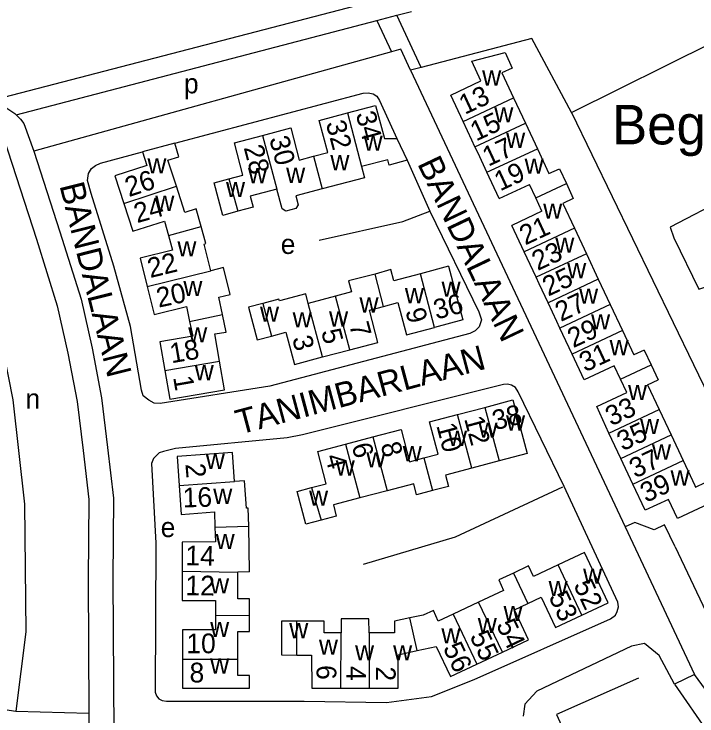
# Model space of a CAD drawing. Extents: x 162883 to 165538, y 383986 to 385172.
# Drawn here: x 163773.3 to 163911.8, y 384315.2 to 384457.6 of the extents above; entities that cross this region are included whole.
import ezdxf

# ---------------------------------------------------------------- set-up
doc = ezdxf.new("R2010")
doc.units = 0
for name, color, linetype in [('BLT_Basislijn', 7, 'Continuous'), ('BLT_Bebouwing', 7, 'Continuous'), ('BLT_Centroide', 7, 'Continuous'), ('BLT_Huisnummer', 7, 'Continuous'), ('BLT_Huisnummer_ tussenligend', 7, 'Continuous'), ('BLT_Onderverdeling_panden', 7, 'Continuous'), ('BLT_Straatnaam', 7, 'Continuous'), ('BLT_Terrein_beschrifting', 7, 'Continuous')]:
    doc.layers.add(name, color=color, linetype=linetype)

msp = doc.modelspace()

# ---------------------------------------------------------------- linework, layer by layer
at = {"layer": 'BLT_Basislijn'}
for p, q in [((163886.33, 384437.63), (163943.9, 384466.17)), ((163850.89, 384457.34), (163853.91, 384458.13)), ((163773.71, 384437.15), (163846.85, 384456.28)), ((163846.85, 384456.28), (163850.89, 384457.34)), ((163853.71, 384446.2), (163897.21, 384353.56)), ((163847.39, 384440.05), (163850.93, 384432.35)), ((163886.33, 384437.63), (163917.29, 384373.57)), ((163853.02, 384427.91), (163857.62, 384417.63)), ((163872.54, 384382.46), (163831.77, 384372.2)), ((163884.83, 384361.77), (163875.54, 384380.97)), ((163831.77, 384372.2), (163828.7, 384371.63)), ((163828.7, 384371.63), (163806.04, 384369.44)), ((163895.71, 384338.26), (163884.83, 384361.77)), ((163802.02, 384350.27), (163801.88, 384320.02)), ((163866.57, 384322.58), (163894.23, 384334.92)), ((163857.95, 384319.18), (163866.57, 384322.58)), ((163899.93, 384322.89), (163883.27, 384315.54)), ((163924.02, 384306.15), (163911.31, 384323.59)), ((163907.2, 384321.69), (163920.41, 384302.58)), ((163804.2, 384318.23), (163832.15, 384318.24)), ((163832.15, 384318.24), (163848.79, 384317.94)), ((163848.79, 384317.94), (163857.95, 384319.18)), ((163788.47, 384315.79), (163788.5, 384310.79)), ((163883.27, 384315.54), (163889.98, 384300.83))]:
    msp.add_line(p, q, dxfattribs=at)
for points in [[(163943.9, 384466.17), (163950.95, 384451.13), (163955.61, 384452.91), (163956.25, 384452.75), (163964.39, 384435.33), (163964.46, 384433.9), (163924.56, 384413.66), (163923.89, 384413.66), (163922.33, 384416.58), (163920.39, 384416.11), (163918.58, 384419.58), (163917.78, 384420.28), (163906.37, 384414.35), (163907.09, 384412.19), (163912.15, 384401.77), (163915.08, 384402.72), (163916.35, 384400.81), (163917.32, 384400.94), (163920.33, 384402.27), (163921.06, 384402.24), (163931.28, 384381.36), (163931.15, 384380.49), (163917.29, 384373.57)], [(163767.22, 384439.42), (163767.75, 384439.83), (163852.89, 384462)], [(163846.85, 384456.28), (163849.84, 384449.9)], [(163855.83, 384446.76), (163850.89, 384457.34)], [(163886.33, 384437.63), (163878.26, 384452.63), (163855.83, 384446.76)], [(163849.84, 384449.9), (163777.32, 384429.79)], [(163853.71, 384446.2), (163851.75, 384450.43), (163849.84, 384449.9)], [(163855.83, 384446.76), (163853.71, 384446.2)], [(163805.88, 384431.37), (163844.09, 384441.52), (163845.07, 384441.57), (163846.08, 384441.41), (163846.83, 384440.93), (163847.39, 384440.05)], [(163767.22, 384439.42), (163769.48, 384439.44), (163771.83, 384438.5), (163773.42, 384437.44), (163773.71, 384437.15)], [(163773.71, 384437.15), (163774.57, 384436.27), (163775.24, 384435.37), (163777.32, 384429.79)], [(163771.24, 384432.37), (163777.82, 384411.92), (163782.06, 384398.43), (163784.2, 384388.81), (163786.05, 384378.99), (163787.3, 384369.05), (163788.43, 384359.12), (163788.31, 384342.96), (163788.47, 384315.79)], [(163777.32, 384429.79), (163782.58, 384413.43), (163786.89, 384399.72), (163789.1, 384389.82), (163790.99, 384379.77), (163792.26, 384369.65), (163793.43, 384359.38), (163793.31, 384342.95), (163793.49, 384311.78)], [(163790.79, 384427.33), (163799.3, 384429.62)], [(163802.92, 384378.61), (163801.67, 384378.68), (163800.6, 384379.26), (163799.49, 384380.17), (163799.11, 384381.31), (163796.92, 384394.21), (163793.51, 384406.47), (163788.89, 384421.21), (163788.16, 384423.82), (163788.38, 384425.21), (163789.02, 384426.27), (163789.78, 384426.87), (163790.79, 384427.33)], [(163749.75, 384422.28), (163752.88, 384421.98), (163757.47, 384420.38), (163761.45, 384417.59), (163764.29, 384413.64), (163769.21, 384398.52), (163773.01, 384379.34), (163775.38, 384358.19), (163775.68, 384332.25), (163773.66, 384316.19)], [(163857.62, 384417.63), (163867.54, 384397.2), (163868.06, 384395.53), (163867.64, 384394.17), (163866.79, 384393.33), (163865.73, 384392.81), (163825.15, 384382.09), (163802.92, 384378.61)], [(163835.13, 384411.73), (163852.16, 384415.53), (163857.62, 384417.63)], [(163875.54, 384380.97), (163874.97, 384381.84), (163874.18, 384382.31), (163873.37, 384382.54), (163872.54, 384382.46)], [(163806.04, 384369.44), (163803.6, 384368.87), (163802.73, 384368.56), (163802.12, 384367.99), (163801.55, 384367.46), (163801.16, 384366.43), (163802.02, 384350.27)], [(163844.14, 384346), (163862.83, 384351.57), (163884.6, 384361.66)], [(163907.39, 384349.55), (163905.21, 384353.97), (163903.1, 384352.95), (163899.15, 384354.42), (163897.21, 384353.56)], [(163897.21, 384353.56), (163911.31, 384323.59), (163907.2, 384321.69), (163904.14, 384327.47), (163901.11, 384329.92), (163898.53, 384329.37), (163879.31, 384320.27), (163876.85, 384317.63), (163876.52, 384315.19)], [(163907.39, 384349.55), (163919.21, 384324.59), (163921.98, 384321.44)], [(163894.23, 384334.92), (163895.26, 384335.65), (163895.61, 384336.41), (163895.86, 384337.33), (163895.71, 384338.26)], [(163801.88, 384320.02), (163802.14, 384319.32), (163802.63, 384318.71), (163803.32, 384318.35), (163804.2, 384318.23)], [(163769.58, 384316.8), (163773.66, 384316.19), (163788.47, 384315.79)]]:
    msp.add_lwpolyline(points, dxfattribs=at)
at = {"layer": 'BLT_Bebouwing'}
for p, q in [((163866.13, 384447.99), (163872.85, 384449.76)), ((163872.85, 384449.76), (163874.33, 384446.61)), ((163867.98, 384444.01), (163866.13, 384447.99)), ((163874.33, 384446.61), (163872.22, 384445.63)), ((163872.22, 384445.63), (163874.59, 384440.56)), ((163861.85, 384441.15), (163867.98, 384444.01)), ((163864.35, 384435.81), (163861.85, 384441.15)), ((163874.59, 384440.56), (163876.99, 384435.42)), ((163876.99, 384435.42), (163879.41, 384430.25)), ((163817.97, 384431.46), (163823.68, 384432.97)), ((163879.41, 384430.25), (163881.77, 384425.21)), ((163871.68, 384420.14), (163869.18, 384425.49)), ((163881.77, 384425.21), (163883.88, 384426.2)), ((163883.88, 384426.2), (163885.29, 384423.18)), ((163793.74, 384424.76), (163795.54, 384419.16)), ((163871.68, 384420.14), (163877.8, 384423)), ((163879.07, 384420.29), (163877.8, 384423)), ((163885.29, 384423.18), (163886.7, 384420.16)), ((163880.34, 384417.57), (163879.07, 384420.29)), ((163886.7, 384420.16), (163884.59, 384419.18)), ((163884.59, 384419.18), (163886.95, 384414.12)), ((163880.34, 384417.57), (163874.24, 384414.71)), ((163876.74, 384409.37), (163874.24, 384414.71)), ((163886.95, 384414.12), (163889.36, 384408.97)), ((163889.36, 384408.97), (163891.77, 384403.81)), ((163861.39, 384406.42), (163855.68, 384404.91)), ((163891.77, 384403.81), (163894.19, 384398.64)), ((163838.46, 384400.35), (163832.96, 384398.9)), ((163894.19, 384398.64), (163896.65, 384393.37)), ((163896.65, 384393.37), (163898.96, 384388.43)), ((163835.85, 384388.02), (163841.4, 384389.49)), ((163901.07, 384389.42), (163898.96, 384388.43)), ((163901.07, 384389.42), (163902.48, 384386.4)), ((163888.9, 384383.39), (163886.45, 384388.62)), ((163895.02, 384386.25), (163888.9, 384383.39)), ((163896.3, 384383.51), (163895.02, 384386.25)), ((163902.48, 384386.4), (163903.89, 384383.38)), ((163897.56, 384380.82), (163896.3, 384383.51)), ((163901.78, 384382.4), (163903.89, 384383.38)), ((163901.78, 384382.4), (163904.14, 384377.35)), ((163891.45, 384377.96), (163897.56, 384380.82)), ((163893.92, 384372.57), (163891.45, 384377.96)), ((163904.14, 384377.35), (163906.55, 384372.2)), ((163896.34, 384367.43), (163893.92, 384372.57)), ((163906.55, 384372.2), (163908.97, 384367.04)), ((163834.86, 384368.84), (163840.52, 384370.34)), ((163806.34, 384367.85), (163806.76, 384361.97)), ((163898.77, 384362.24), (163896.34, 384367.43)), ((163830.63, 384334.42), (163827.55, 384334.42)), ((163836.17, 384334.42), (163830.63, 384334.42)), ((163836.17, 384332.09), (163836.17, 384334.42)), ((163839.59, 384332.09), (163836.17, 384332.09)), ((163807.42, 384326.76), (163807.42, 384320.87)), ((163818.68, 384323.41), (163818.69, 384326.74)), ((163821.01, 384323.41), (163818.68, 384323.41)), ((163821.02, 384320.87), (163821.01, 384323.41)), ((163807.42, 384320.87), (163821.02, 384320.87))]:
    msp.add_line(p, q, dxfattribs=at)
for points in [[(163840.88, 384437.53), (163846.59, 384439.04), (163848.38, 384432.33), (163850.93, 384432.35)], [(163835.18, 384436.02), (163840.88, 384437.53)], [(163834.01, 384428.73), (163836.9, 384429.5), (163835.18, 384436.02)], [(163866.76, 384430.64), (163866.15, 384431.97), (163864.35, 384435.81)], [(163823.68, 384432.97), (163829.39, 384434.47)], [(163829.39, 384434.47), (163831.11, 384427.97), (163834.01, 384428.73)], [(163850.93, 384432.35), (163853.02, 384427.91)], [(163805.88, 384431.37), (163799.3, 384429.62)], [(163806.21, 384422.66), (163804.49, 384427.95), (163806.73, 384428.64), (163805.88, 384431.37)], [(163816.81, 384424.15), (163819.71, 384424.93), (163817.97, 384431.46)], [(163869.18, 384425.49), (163867.39, 384429.33), (163866.76, 384430.64)], [(163799.3, 384429.62), (163800.2, 384426.84), (163793.74, 384424.76)], [(163853.02, 384427.91), (163849.38, 384426.94), (163849.09, 384428.03), (163843.77, 384426.64)], [(163843.77, 384426.64), (163844.37, 384424.39), (163835.77, 384422.11)], [(163818.7, 384417.57), (163815.6, 384416.73), (163813.84, 384423.35), (163816.81, 384424.15)], [(163811.22, 384414.5), (163810.2, 384418.07), (163807.93, 384417.34), (163806.21, 384422.66)], [(163826.57, 384422.07), (163821.2, 384420.64), (163821.79, 384418.4), (163818.7, 384417.57)], [(163835.77, 384422.11), (163830.41, 384420.69), (163830.88, 384418.9), (163830.42, 384418.11), (163828.43, 384417.58), (163827.63, 384418.04), (163826.57, 384422.07)], [(163795.54, 384419.16), (163797.36, 384413.52)], [(163797.36, 384413.52), (163803.78, 384415.59), (163804.61, 384412.63)], [(163813.19, 384405.5), (163811.86, 384410.92), (163812.2, 384411.07), (163811.22, 384414.5)], [(163804.61, 384412.63), (163805.43, 384409.69), (163798.88, 384408.06)], [(163879.14, 384404.2), (163878.54, 384405.53), (163876.74, 384409.37)], [(163798.88, 384408.06), (163800.3, 384402.35)], [(163861.39, 384406.42), (163864.28, 384395.53), (163858.58, 384394.03)], [(163815.55, 384396.64), (163814.84, 384400.18), (163817.09, 384400.73), (163815.77, 384406.14), (163813.19, 384405.5)], [(163855.68, 384404.91), (163850.29, 384403.48), (163849.7, 384405.74), (163846.5, 384404.82)], [(163846.5, 384404.82), (163841.11, 384403.47), (163841.7, 384401.21), (163838.46, 384400.35)], [(163881.58, 384399.03), (163879.77, 384402.89), (163879.14, 384404.2)], [(163800.3, 384402.35), (163801.72, 384396.61)], [(163832.96, 384398.9), (163832.45, 384400.85), (163827.09, 384399.43), (163827.01, 384399.74), (163823.71, 384398.86)], [(163801.72, 384396.61), (163808.26, 384398.24), (163808.88, 384395.24)], [(163823.71, 384398.86), (163820.82, 384398.1), (163822.57, 384391.49), (163825.49, 384392.25)], [(163847.07, 384390.99), (163845.34, 384397.52), (163848.24, 384398.28)], [(163848.24, 384398.28), (163851.14, 384399.05), (163852.86, 384392.52)], [(163883.98, 384393.86), (163883.36, 384395.22), (163881.58, 384399.03)], [(163814.96, 384387.19), (163814.02, 384392.69), (163816.29, 384393.08), (163815.55, 384396.64)], [(163808.88, 384395.24), (163809.51, 384392.24), (163802.87, 384391.09)], [(163852.86, 384392.52), (163858.58, 384394.03)], [(163886.45, 384388.62), (163884.61, 384392.56), (163883.98, 384393.86)], [(163825.49, 384392.25), (163828.42, 384393.03), (163830.15, 384386.51), (163835.85, 384388.02)], [(163802.87, 384391.09), (163803.87, 384385.28)], [(163841.4, 384389.49), (163847.07, 384390.99)], [(163804.88, 384379.47), (163815.96, 384381.38), (163814.96, 384387.19)], [(163803.87, 384385.28), (163804.88, 384379.47)], [(163868.77, 384377.8), (163874.47, 384379.32), (163877.36, 384368.43), (163871.7, 384366.93)], [(163863.23, 384376.34), (163868.77, 384377.8)], [(163857.56, 384374.84), (163863.23, 384376.34)], [(163856.4, 384367.55), (163859.3, 384368.32), (163857.56, 384374.84)], [(163846.05, 384371.8), (163851.77, 384373.31)], [(163851.77, 384373.31), (163853.5, 384366.79), (163856.4, 384367.55)], [(163840.52, 384370.34), (163846.05, 384371.8)], [(163818, 384362.77), (163817.57, 384368.66), (163806.34, 384367.85)], [(163833.62, 384361.54), (163836.56, 384362.32), (163834.86, 384368.84)], [(163871.7, 384366.93), (163866.15, 384365.45)], [(163908.97, 384367.04), (163911.33, 384361.98), (163911.49, 384361.65), (163915.42, 384363.49), (163917.2, 384359.67), (163907.8, 384355.28)], [(163866.15, 384365.45), (163860.79, 384364.03), (163861.38, 384361.77), (163858.15, 384360.92)], [(163820.87, 384353.72), (163820.74, 384357.37), (163820.41, 384357.35), (163820, 384362.91), (163818, 384362.77)], [(163854.93, 384360.07), (163854.34, 384362.32), (163848.94, 384360.9)], [(163907.8, 384355.28), (163905.99, 384359.13), (163901.27, 384356.92), (163898.77, 384362.24)], [(163806.76, 384361.97), (163807.17, 384356.09)], [(163830.7, 384360.76), (163833.62, 384361.54)], [(163848.94, 384360.9), (163843.41, 384359.43)], [(163858.15, 384360.92), (163854.93, 384360.07)], [(163835.54, 384354.95), (163832.46, 384354.13), (163830.7, 384360.76)], [(163843.41, 384359.43), (163838.04, 384358.02), (163838.64, 384355.77), (163835.54, 384354.95)], [(163807.17, 384356.09), (163813.93, 384356.61), (163814.03, 384353.52)], [(163821.01, 384344.42), (163820.87, 384353.72)], [(163814.03, 384353.52), (163814.14, 384350.5), (163807.39, 384350.45)], [(163807.39, 384350.45), (163807.41, 384348.73), (163807.41, 384344.55)], [(163888.41, 384335.69), (163893.75, 384338.19), (163888.98, 384348.37), (163883.64, 384345.87)], [(163883.64, 384345.87), (163878.6, 384343.51), (163877.6, 384345.63), (163874.57, 384344.2)], [(163807.41, 384344.55), (163807.41, 384338.66)], [(163821.01, 384344.42), (163818.68, 384344.41)], [(163821.01, 384335.6), (163821.01, 384339), (163818.68, 384339), (163818.68, 384344.41)], [(163874.57, 384344.2), (163871.58, 384342.79), (163872.57, 384340.68), (163867.48, 384338.29)], [(163807.41, 384338.66), (163814.16, 384338.66), (163814.16, 384335.68)], [(163867.48, 384338.29), (163862.35, 384335.89)], [(163877.62, 384330.64), (163874.76, 384336.75), (163877.48, 384338.02)], [(163877.48, 384338.02), (163880.2, 384339.3), (163883.06, 384333.18)], [(163814.16, 384335.68), (163814.16, 384332.67), (163807.42, 384332.67)], [(163818.69, 384326.74), (163818.68, 384332.34), (163821.01, 384332.34), (163821.01, 384335.6)], [(163862.35, 384335.89), (163859.31, 384334.47), (163858.32, 384336.58), (163856.28, 384335.68), (163853.55, 384335.11)], [(163883.06, 384333.18), (163888.41, 384335.69)], [(163827.55, 384334.42), (163827.55, 384327.58), (163830.61, 384327.56)], [(163845.29, 384332.09), (163845.21, 384334.92), (163839.63, 384334.93), (163839.59, 384332.09)], [(163853.55, 384335.11), (163850.47, 384334.46), (163850.47, 384332.09), (163845.29, 384332.09)], [(163807.42, 384332.67), (163807.42, 384326.76)], [(163872.32, 384328.16), (163877.62, 384330.64)], [(163845.3, 384320.86), (163851.17, 384320.86), (163851.17, 384327.59), (163855.03, 384328.46)], [(163855.03, 384328.46), (163858.91, 384329.33), (163861.78, 384323.22), (163867.13, 384325.72)], [(163867.13, 384325.72), (163872.32, 384328.16)], [(163830.61, 384327.56), (163833.64, 384327.55), (163833.67, 384320.86)], [(163833.67, 384320.86), (163839.56, 384320.86)], [(163839.56, 384320.86), (163845.3, 384320.86)]]:
    msp.add_lwpolyline(points, dxfattribs=at)
at = {"layer": 'BLT_Onderverdeling_panden'}
for p, q in [((163864.35, 384435.81), (163874.59, 384440.56)), ((163840.88, 384437.53), (163843.77, 384426.64)), ((163866.76, 384430.64), (163876.99, 384435.42)), ((163823.68, 384432.97), (163826.57, 384422.07)), ((163869.18, 384425.49), (163879.41, 384430.25)), ((163834.01, 384428.73), (163835.77, 384422.11)), ((163816.81, 384424.15), (163818.7, 384417.57)), ((163795.54, 384419.16), (163806.21, 384422.66)), ((163879.07, 384420.29), (163885.29, 384423.18)), ((163804.61, 384412.63), (163811.22, 384414.5)), ((163886.95, 384414.12), (163876.74, 384409.37)), ((163889.36, 384408.97), (163879.14, 384404.2)), ((163800.3, 384402.35), (163813.19, 384405.5)), ((163848.24, 384398.28), (163846.5, 384404.82)), ((163858.58, 384394.03), (163855.68, 384404.91)), ((163891.77, 384403.81), (163881.58, 384399.03)), ((163841.4, 384389.49), (163838.46, 384400.35)), ((163823.71, 384398.86), (163825.49, 384392.25)), ((163835.85, 384388.02), (163832.96, 384398.9)), ((163894.19, 384398.64), (163883.98, 384393.86)), ((163808.88, 384395.24), (163815.55, 384396.64)), ((163896.65, 384393.37), (163886.45, 384388.62)), ((163896.3, 384383.51), (163902.48, 384386.4)), ((163868.77, 384377.8), (163871.7, 384366.93)), ((163893.92, 384372.57), (163904.14, 384377.35)), ((163866.15, 384365.45), (163863.23, 384376.34)), ((163896.34, 384367.43), (163906.55, 384372.2)), ((163846.05, 384371.8), (163848.94, 384360.9)), ((163840.52, 384370.34), (163843.41, 384359.43)), ((163856.4, 384367.55), (163858.15, 384360.92)), ((163898.77, 384362.24), (163908.97, 384367.04)), ((163806.76, 384361.97), (163818, 384362.77)), ((163833.62, 384361.54), (163835.54, 384354.95)), ((163814.03, 384353.52), (163820.87, 384353.72)), ((163888.41, 384335.69), (163883.64, 384345.87)), ((163807.41, 384344.55), (163818.68, 384344.41)), ((163874.57, 384344.2), (163877.48, 384338.02)), ((163872.32, 384328.16), (163867.48, 384338.29)), ((163814.16, 384335.68), (163821.01, 384335.6)), ((163862.35, 384335.89), (163867.13, 384325.72)), ((163830.61, 384327.56), (163830.63, 384334.42)), ((163855.03, 384328.46), (163853.55, 384335.11)), ((163839.56, 384320.86), (163839.59, 384332.09)), ((163845.29, 384332.09), (163845.3, 384320.86)), ((163807.42, 384326.76), (163818.69, 384326.74))]:
    msp.add_line(p, q, dxfattribs=at)
msp.add_lwpolyline([(163803.87, 384385.28), (163814.96, 384387.19)], dxfattribs=at)

# ---------------------------------------------------------------- texts
at = {"layer": 'BLT_Centroide'}
for s, p in [('w', (163868.22, 384443.06)), ('p', (163807.74, 384441.49)), ('w', (163870.68, 384435.59)), ('w', (163873.08, 384430.44)), ('w', (163844.18, 384429.84)), ('w', (163800.33, 384425.25)), ('w', (163837.43, 384425.89)), ('w', (163876.83, 384425.19)), ('w', (163820.74, 384423.27)), ('w', (163828.46, 384423.33)), ('w', (163816.27, 384420.45)), ('w', (163801.93, 384417.66)), ('w', (163880.59, 384416.08)), ('e', (163827.37, 384408.92)), ('w', (163883.05, 384409.16)), ('w', (163806.41, 384408.44)), ('w', (163885.46, 384404)), ('w', (163807.62, 384400.38)), ('w', (163859.98, 384400.23)), ('w', (163852.55, 384398.92)), ('w', (163887.88, 384398.84)), ('w', (163843.34, 384397.02)), ('w', (163823.16, 384395.17)), ('w', (163829.78, 384394.02)), ('w', (163837.17, 384394.19)), ('w', (163890.31, 384393.62)), ('w', (163808.6, 384390.97)), ('w', (163894.06, 384388.38)), ('w', (163809.92, 384383.31)), ('w', (163897.8, 384379.3)), ('n', (163775.6, 384377.55)), ('w', (163873.06, 384373.11)), ('w', (163900.24, 384372.38)), ('w', (163867.47, 384371.64)), ('w', (163861.28, 384369.98)), ('w', (163852.11, 384366.88)), ('w', (163902.66, 384367.22)), ('w', (163812.16, 384365.31)), ('w', (163844.73, 384365.61)), ('w', (163838.52, 384363.98)), ('w', (163906.42, 384361.94)), ('w', (163813.68, 384358.22)), ('w', (163833.12, 384357.86)), ('e', (163803.02, 384351.49)), ('w', (163814.17, 384349.06)), ('w', (163888.69, 384342.03)), ('w', (163813.04, 384340.06)), ('w', (163881.69, 384339.53)), ('w', (163872.55, 384334.47)), ('w', (163813.05, 384331.22)), ('w', (163829.09, 384330.98)), ('w', (163867.33, 384332.02)), ('w', (163859.95, 384329.91)), ('w', (163835.11, 384327.64)), ('w', (163842.44, 384326.48)), ('w', (163850.16, 384326.48)), ('w', (163813.05, 384323.81))]:
    msp.add_text(s, height=4, dxfattribs=at).set_placement(p)
at = {"layer": 'BLT_Huisnummer'}
for s, rotation, p in [('13', 24.9028, (163864.7, 384437.12)), ('34', 284.8652, (163842.55, 384437.33)), ('32', 284.9083, (163836.48, 384435.47)), ('30', 284.8103, (163825.01, 384432.32)), ('28', 284.8849, (163819.83, 384430.5)), ('19', 24.9229, (163871.86, 384421.59)), ('26', 18.1638, (163796.56, 384420.44)), ('24', 15.6393, (163798.22, 384415.15)), ('21', 24.9659, (163876.96, 384410.63)), ('22', 13.7598, (163800.9, 384404.02)), ('25', 25.1026, (163881.62, 384400.25)), ('20', 11.9021, (163802.6, 384398.02)), ('36', 14.7624, (163858.94, 384395.59)), ('9', 284.9243, (163852.61, 384397.42)), ('7', 285.0917, (163841.21, 384394.56)), ('3', 284.9095, (163829.65, 384391.83)), ('18', 9.757, (163805.21, 384386.74)), ('31', 25.0973, (163889.09, 384384.88)), ('1', 279.8313, (163805.53, 384383.9)), ('33', 25.0359, (163894.39, 384373.93)), ('38', 14.8573, (163870.86, 384373.12)), ('10', 284.8537, (163858.9, 384374.11)), ('8', 284.8451, (163847.59, 384370.26)), ('4', 284.7695, (163836.32, 384367.84)), ('2', 275.0312, (163808.02, 384366.31)), ('39', 25.1427, (163901.46, 384358.4)), ('16', 1.6138, (163807.55, 384357.5)), ('14', 358.59, (163807.99, 384345.8)), ('12', 359.316, (163808.04, 384339.71)), ('52', 295.1401, (163886.67, 384341.78)), ('53', 295.1241, (163881.63, 384339.4)), ('54', 295.5049, (163870.99, 384333.71)), ('10', 359.8984, (163808.23, 384327.94)), ('56', 295.1072, (163860.2, 384329.05)), ('8', 0.0631, (163808.88, 384322.01)), ('6', 270.2657, (163834.64, 384325.52)), ('2', 270.0205, (163846.67, 384325.25))]:
    msp.add_text(s, height=4, rotation=rotation, dxfattribs=at).set_placement(p)
at = {"layer": 'BLT_Huisnummer_ tussenligend'}
for s, rotation, p in [('15', 24.8134, (163866.98, 384431.72)), ('17', 24.9626, (163869.46, 384426.59)), ('23', 25.0319, (163879.47, 384405.45)), ('27', 24.9987, (163884.18, 384395.11)), ('29', 24.9888, (163886.69, 384389.79)), ('5', 284.8731, (163835.53, 384393.22)), ('12', 285.0459, (163864.54, 384375.51)), ('35', 25.024, (163896.71, 384368.87)), ('6', 284.848, (163841.72, 384370.08)), ('37', 25.1757, (163899.25, 384363.36)), ('55', 295.2047, (163865.62, 384331.39)), ('4', 269.846, (163840.66, 384325.36))]:
    msp.add_text(s, height=4, rotation=rotation, dxfattribs=at).set_placement(p)
at = {"layer": 'BLT_Straatnaam'}
for s, rotation, p in [('BANDALAAN', 295.4346, (163855, 384427.24)), ('BANDALAAN', 284.1211, (163782.47, 384422.81)), ('TANIMBARLAAN', 14.9661, (163819, 384372.25))]:
    msp.add_text(s, height=5, rotation=rotation, dxfattribs=at).set_placement(p)
at = {"layer": 'BLT_Terrein_beschrifting'}
msp.add_text('Begraafplaats', height=8, rotation=359.8938, dxfattribs=at).set_placement((163894.55, 384431.16))

doc.saveas('drawing.dxf')
